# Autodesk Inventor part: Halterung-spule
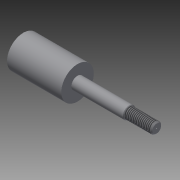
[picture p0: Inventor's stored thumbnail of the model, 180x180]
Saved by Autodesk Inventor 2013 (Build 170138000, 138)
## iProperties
Created: 2013-02
Part Number: Halterung-spule
Material: Allgemein
Document SubType Name: Modeling
Designer: ledam_000
Density: 1 g/cm^3
Author: ledam_000
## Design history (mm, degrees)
sketch "Skizze1"
  geometry: L1 (0, 0)-(-52, 0); L2 (0, 0)-(50, 0); L3 (50, 0)-(50, 15); L4 (50, 15)-(0, 15); L5 (0, 15)-(0, 5.7); L6 (0, 5.7)-(-48, 5.7); L7 (-48, 5.7)-(-48, 5); L8 (-48, 5)-(-73, 5); L9 (-73, 5)-(-73, 0); L10 (-73, 0)-(-52, 0)
  constraints: 20 end point, 5 parallel, 3 perpendicular, 1 collinear, 1 horizontal, 1 point on line
  dimensions: "d2" = 15 distance of L2.end L3.end; "d5" = 25 distance of L7.end L8.end; "d12" = 48 distance of L5.end L6.end; "d13" = 5.7 distance between parallel lines of L1 L6; "d14" = 50 distance between parallel lines of L3 L5; "d29" = 5 distance of L8.end L9.end
revolve "Umdrehung1" sketch "Skizze1" stored, may be unused: angle "d6" = 90 deg
feature "Gewinde1" dims "d7" = 10, "d8" = 0
chamfer "Fase1" distance "d9" = 1; stored, may be unused: second distance "d10" = 2, angle "d11" = 45 deg
hole "Bohrung1" diameter "d17" = 1; stored, may be unused: countersink angle "d21" = 90 deg, drill point angle "d23" = 118 deg; dims "d18" = 6, "d19" = 5, "d20" = 2, "d22" = 1, "d24" = 10, "d25" = 10
chamfer "Fase2" distance "d26" = 0.5; stored, may be unused: second distance "d27" = 2, angle "d28" = 45 deg
node "Volumenkörper1"
